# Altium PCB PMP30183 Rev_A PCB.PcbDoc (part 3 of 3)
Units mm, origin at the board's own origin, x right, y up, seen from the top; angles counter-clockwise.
Board outline 88.14 x 173.35 mm, 4 copper layers (Top Layer, Signal Layer 1, Signal Layer 2, Bottom Layer), stack 2.028 mm thick; 250 components, 133 nets, 589 pads, 226 vias.
Unrouted connection lines stored in the file: 1.
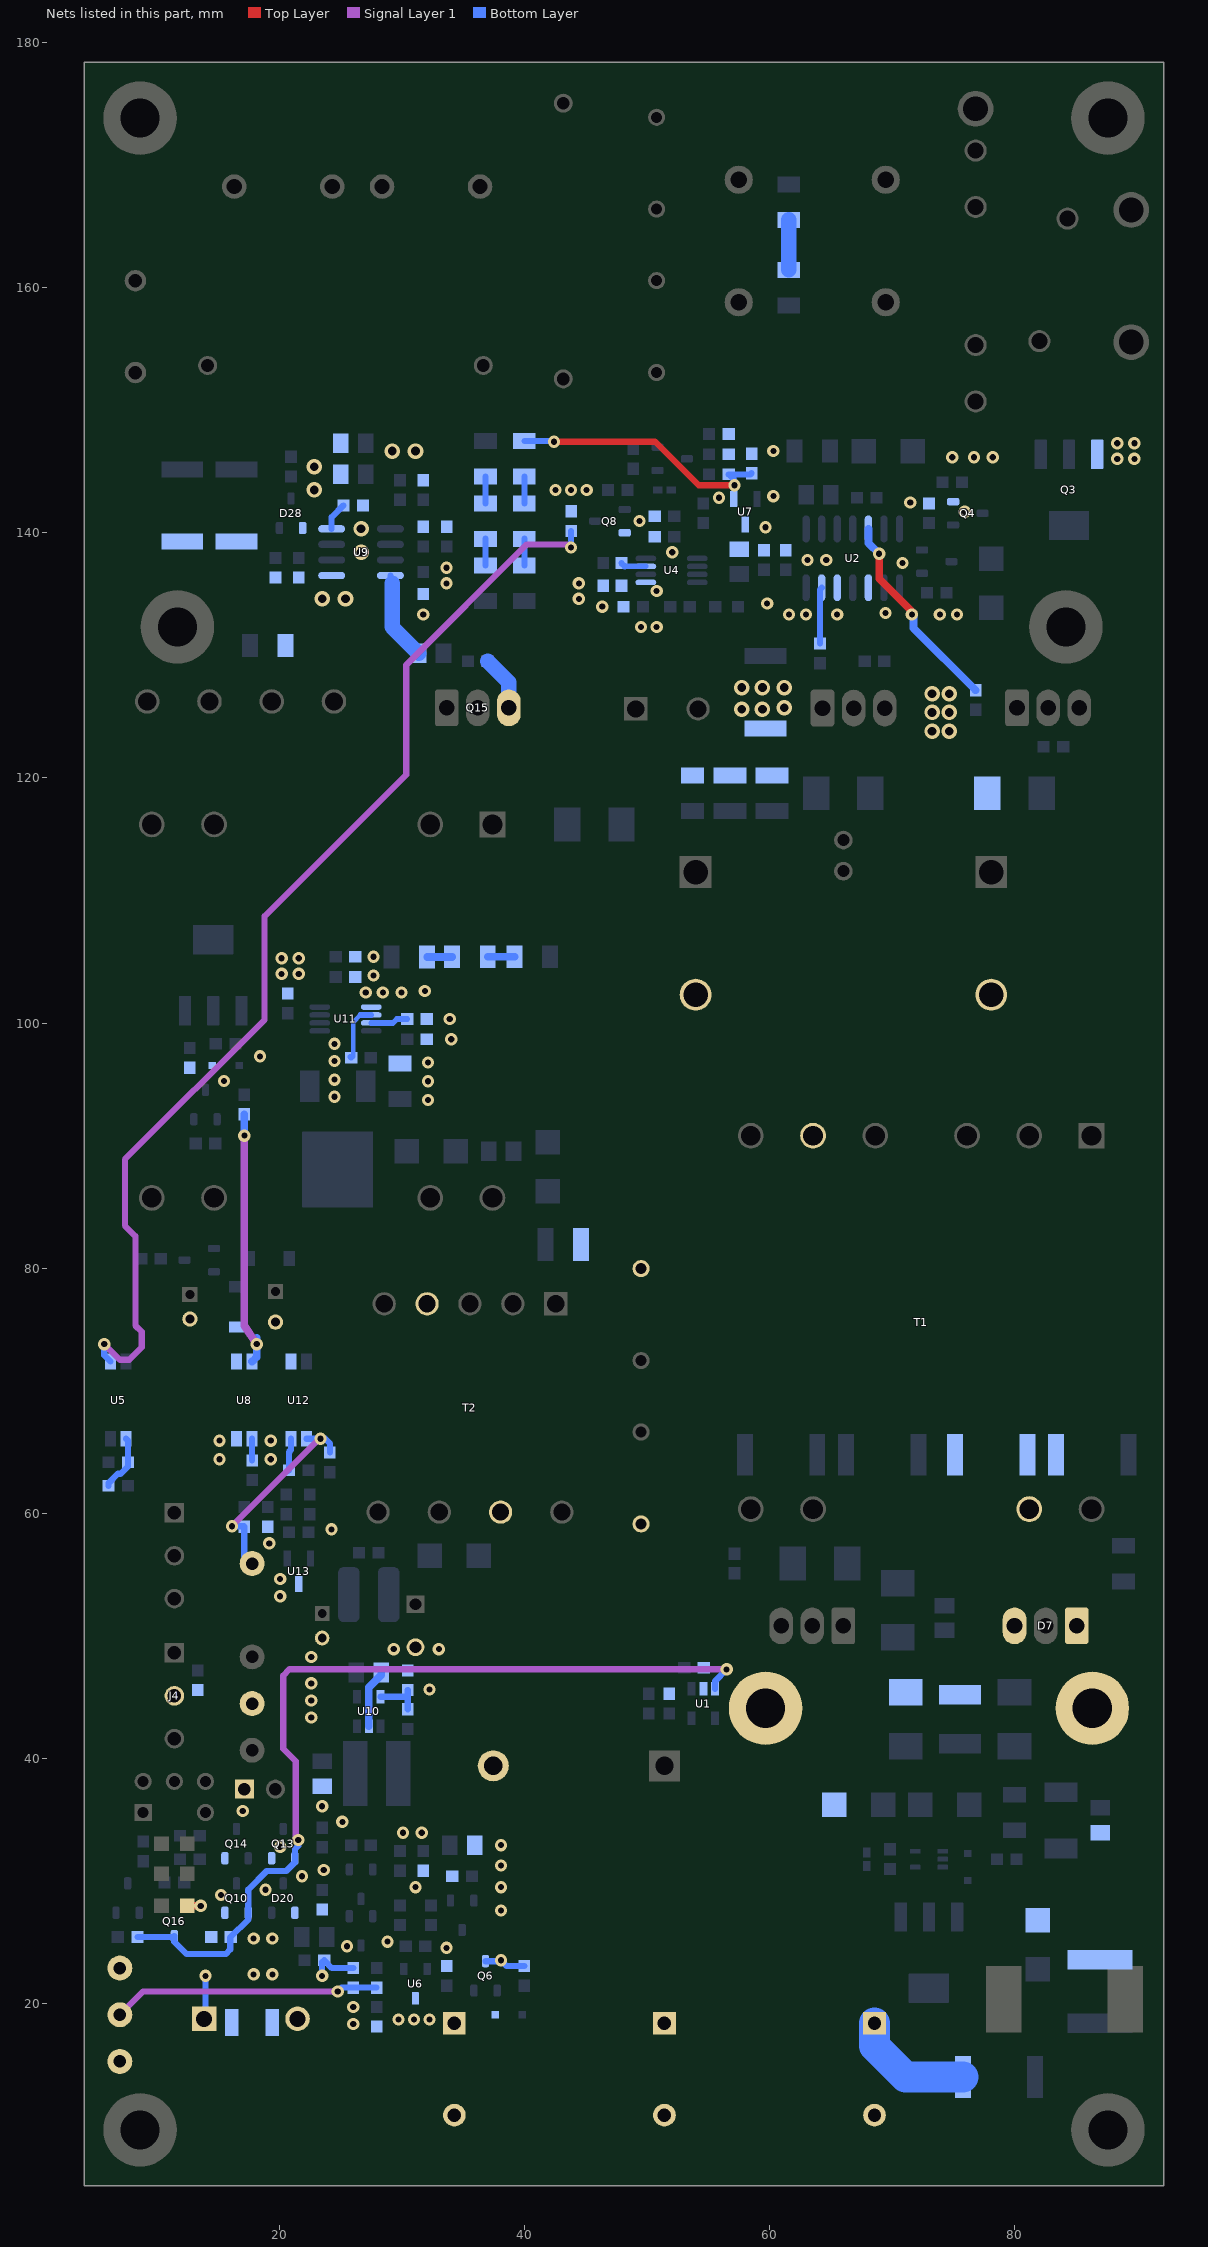
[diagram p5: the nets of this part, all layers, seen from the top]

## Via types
v1: diameter 1, hole 0.5, Top Layer to Bottom Layer, 163 vias
v2: diameter 1.27, hole 0.711, Top Layer to Bottom Layer, 63 vias

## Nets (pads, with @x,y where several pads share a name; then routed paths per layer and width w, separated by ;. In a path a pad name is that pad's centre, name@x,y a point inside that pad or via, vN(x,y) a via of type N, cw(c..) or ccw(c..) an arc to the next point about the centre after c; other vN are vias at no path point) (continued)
NetR7_1: R7.1 U2.12 | length 17.3
  Top Layer w0.635: v1@68.961,138.43 v1(68.961,138.303) 68.961,136.271 71.755,133.477 v1(71.628,133.35)
  Bottom Layer w0.635: U2.12@68.08,140.329 68.08,139.184 v1(68.961,138.303) ; v1(71.628,133.35) 71.755,133.477 71.755,132.245 R7.1@76.835,127.165
NetR9_1: R9.1 R12.2
NetR10_1: R10.1 U2.6 | length 4.6
  Bottom Layer w0.508: R10.1@64.135,130.975 64.135,135.393 U2.6@64.27,135.529
NetR19_1: R19.1 R23.2 U5.1 | length 4.7
  Bottom Layer w0.508: R19.1@6.058,62.23 6.058,62.442 6.829,63.213 7.041,63.213 7.658,63.83 R23.2@7.658,64.135 7.658,65.9 U5.1@7.493,66.065
NetR20_1: R20.1 R25.2 | length 2.2
  Bottom Layer w0.508: R20.1@40.005,137.34 R25.2@40.005,139.52
NetR25_1: R25.1 R29.2 | length 2.2
  Bottom Layer w0.508: R25.1@40.005,142.42 R29.2@40.005,144.6
NetR26_2: R26.2 U4.7 | length 2.1
  Bottom Layer w0.457: R26.2@48.204,137.267 U4.7@49.917,137.267
  Bottom Layer w0.508: R26.2@47.927,137.544 R26.2@48.204,137.267
NetR29_1: R29.1 R30.1 R38.2 U7.1 | length 21.7
  Top Layer w0.508: v1(42.418,147.447) 50.673,147.447 54.229,143.891 v1(57.15,143.891)
  Bottom Layer w0.508: R29.1@40.005,147.5 42.365,147.5 v1(42.418,147.447) ; v1(57.15,143.891) 57.089,143.891 57.089,144.371 R30.1@56.68,144.78 58.458,144.78 R38.2@58.547,144.869
NetR32_2: R32.2 R34.2 TP9.1 | length 21.9
  Signal Layer 1 w0.508: TP9.1@6.985,19.05 8.89,20.955 v1(24.765,20.955)
  Bottom Layer w0.508: v1(24.765,20.955) 25.075,21.265 R32.2@26.035,21.265 R34.2@27.94,21.265
NetR52_1: R52.1 U8.4 | length 21.2
  Signal Layer 1 w0.635: v1(17.145,90.805) 17.145,75.311 v1(18.161,73.787)
  Bottom Layer w0.635: v1(17.145,90.805) R52.1@17.145,92.545 ; U8.4@17.78,72.365 18.161,72.746 18.161,74.295
NetR53_1: R53.1 U8.1 | length 1.8
  Bottom Layer w0.508: R53.1@17.78,64.3 U8.1@17.78,66.065
NetR55_1: R55.1 R60.2 | length 4.1
  Bottom Layer w1.27: R55.1@61.595,161.47 R60.2@61.595,165.555
NetR56_1: R56.1 R59.2 | length 2.2
  Bottom Layer w0.508: R56.1@36.83,137.34 R59.2@36.83,139.52
NetR57_2: R57.2 U9.8 | length 7.3
  Bottom Layer w0.508: U9.8@29.07,136.525 29.07,136.03 29.21,135.89
  Bottom Layer w1.27: 29.21,135.89 29.21,132.334 R57.2@31.369,130.175
NetR59_1: R59.1 R62.2 | length 2.2
  Bottom Layer w0.508: R59.1@36.83,142.42 R62.2@36.83,144.6
NetR68_2: R68.2 U5.3 | length 90.5
  Signal Layer 1 w0.508: v1(5.715,73.787) 6.985,72.517 7.747,72.517 8.763,73.533 8.763,74.803 8.255,75.311 8.255,82.612 7.397,83.47 7.397,88.869 18.796,100.268 18.796,108.712 30.353,120.269 30.353,129.224 40.194,139.065 43.815,139.065 v1(43.815,138.811)
  Bottom Layer w0.508: v1(5.715,73.787) 5.715,72.873 U5.3@6.223,72.365 ; v1(43.815,138.811) R68.2@43.815,140.17
NetR69_2: R69.2 U9.4 | length 2.3
  Bottom Layer w0.508: U9.4@24.27,140.335 24.27,141.275 R69.2@25.235,142.24
NetR71_1: R71.1 R73.2 | length 2.2
  Bottom Layer w0.635: R73.2@37.01,105.41 R71.1@39.19,105.41
NetR73_1: R73.1 R75.2 | length 2
  Bottom Layer w0.635: R75.2@32.071,105.385 34.085,105.385 R73.1@34.11,105.41
NetR77_1: R77.1 R83.2 TP28.1 U12.1 | length 17.3
  Signal Layer 1 w0.508: v1(16.129,58.928) 23.266,66.065 v1(23.368,66.065)
  Bottom Layer w0.508: v1(16.129,58.928) 17.107,58.928 R83.2@17.145,58.89 17.145,56.515 TP28.1@17.78,55.88 ; U12.1@22.225,66.065 v1(23.368,66.065) 23.75,66.065 24.13,65.685 R77.1@24.13,64.935
NetR78_1: R78.1 R80.2 U10.5 | length 3.9
  Bottom Layer w0.508: U10.5@28.255,45.015 30.296,45.015 30.48,44.831 ; R78.1@30.48,43.98 30.48,44.831 ; R80.2@30.48,45.555 30.48,44.831
NetR79_1: R79.1 U11.6 | length 4.7
  Bottom Layer w0.381: R79.1@26.035,97.244 26.035,100.076 26.614,100.655
  Bottom Layer w0.457: R79.1@25.781,97.244 R79.1@25.87,97.155 ; 26.614,100.655 U11.6@27.5,100.655
NetR82_2: R82.2 U11.7 | length 3.1
  Bottom Layer w0.457: U11.7@27.5,100.005 29.266,100.005 29.591,100.33 R82.2@30.442,100.33
NetR84_2: R84.2 U12.2 | length 2.6
  Bottom Layer w0.508: R84.2@20.79,63.5 20.79,64.986 20.955,65.151 U12.2@20.955,66.065
OVER_TEMPERATURE: Q10.1 Q13.1 Q16.3 R43.2 R47.2 U1.3 | length 73.1
  Signal Layer 1 w0.508: v1(21.545,33.319) 21.336,33.528 21.336,39.751 20.32,40.767 20.32,46.736 20.828,47.244 50.165,47.244 v1(56.515,47.244)
  Bottom Layer w0.508: R43.2@8.42,25.4 11.36,25.4 Q16.3@11.43,25.47 11.43,25.019 12.446,24.003 15.621,24.003 16.002,24.384 16.002,25.362 R47.2@16.04,25.4 17.46,26.82 Q10.1@17.46,27.375 17.46,29.271 18.972,30.783 20.574,30.783 21.27,31.479 Q13.1@21.27,31.82 21.27,32.57 21.545,32.845 v1(21.545,33.319) ; U1.3@55.56,45.65 55.56,46.289 v1(56.515,47.244)
PGND: C1.2 C2.2 C3.2 C7.2 C15.1 C18.2 C21.2 C23.2 C24.2 C25.2 C27.2 C29.2 C32.2 C33.1 C35.2 C36.2 C39.2 C40.2 C41.2 C42.2 C43.2 C44.2 C45.2 C46.2 C50.2 C53.2 C54.2 C55.2 C56.2 C57.2 D8.2 D28.1 D29.2 D35.2 Q3.3 Q4.2 Q8.2 Q15.3 R14.1 R26.1 R38.1 R39.1 R51.2 R58.1 R61.2 R63.2 R66.1 R68.1 R69.1 R81.1 R82.1 T1.5 T2.4 U2.3 U2.5 U4.5 U7.3 U8.3 U9.1 U11.5 U12.3 | length 4.5
  Bottom Layer w1.27: R58.1@36.995,129.54 38.735,127.8 Q15.3@38.735,125.73
  other v1: 32.131,93.726 24.511,93.98 32.131,95.25 15.494,95.27 24.511,95.377 32.131,96.774 24.511,96.901 18.415,97.282 24.511,98.298 34.036,98.679 33.909,100.33 27.051,102.489 28.448,102.489 29.972,102.489 31.877,102.616 27.686,103.886 20.193,104.013 21.59,104.013 20.193,105.283 21.59,105.283 27.686,105.41 49.53,132.334 50.8,132.334 31.75,133.35 61.595,133.35 62.992,133.35 65.532,133.35 73.914,133.35 75.311,133.35 69.469,133.477 46.355,133.985 59.817,134.239 44.45,134.62 50.8,135.255 33.655,135.89 44.45,135.89 33.655,137.16 70.866,137.541 63.119,137.795 64.643,137.795 52.07,138.43 59.69,140.462 49.403,140.97 75.946,141.732 71.501,142.494 55.88,142.875 60.325,143.002 42.545,143.51 43.815,143.51 45.085,143.51 88.392,146.05 89.789,146.05 74.93,146.177 76.708,146.177 78.232,146.177 60.325,146.685 88.392,147.32 89.789,147.32
  other v2: 73.279,123.825 74.676,123.825 73.279,125.349 74.676,125.349 57.74,125.603 59.436,125.603 61.214,125.73 73.279,126.873 74.676,126.873 57.74,127.381 59.436,127.381 61.214,127.381 23.495,134.62 25.4,134.62 26.67,138.43 26.67,140.335 22.86,143.51 22.86,145.415 29.21,146.685 31.115,146.685
SGND: C5.2 C10.2 C11.2 C12.2 C13.2 C14.2 C16.2 C17.2 C20.2 C28.2 C31.2 C47.2 C48.2 C49.2 C51.2 C52.2 D7.1 D7.3 D11.2 D15.2 D16.2 D17.2 D20.1 D23.2 J2.2 J4.2 J5.1 Q10.2 Q13.2 Q14.2 Q16.2 R4.2 R12.1 R36.1 R40.2 R47.1 R48.2 R49.1 R80.1 R86.1 T1.11 T2.8 TP2.1 TP4.1 TP10.1 TP24.1 U1.2 U6.3 U8.2 U10.2 U13.3 | length 5.9
  Top Layer w0.635: D23.2@12.48,27.94 v1(13.589,27.94)
  Bottom Layer w0.635: U10.2@27.305,42.615 27.305,45.763 28.321,46.779 C51.2@28.321,46.99
  other v1: 26.035,18.288 29.718,18.669 30.988,18.669 32.258,18.669 26.035,19.685 17.907,22.352 19.431,22.352 33.655,24.511 25.527,24.638 28.829,25.019 17.907,25.273 19.431,25.273 38.1,27.559 15.24,28.829 18.87,29.25 31.115,29.464 38.1,29.464 21.844,30.353 23.622,30.861 38.1,31.242 20.066,32.766 38.1,32.893 30.099,33.909 31.623,33.909 25.146,34.798 17.018,35.687 23.495,36.068 22.606,43.307 22.606,44.704 32.258,45.593 22.606,46.101 22.606,48.26 29.337,48.895 33.02,48.895 20.066,53.213 20.066,54.61 19.177,57.531 24.257,58.674 15.113,64.389 19.304,64.389 15.113,65.913 19.304,65.913
VOUT: C10.1 C11.1 C12.1 C13.1 J2.1 L1.2 Q6.3 R21.1 R28.1 R32.1 R37.2 TP3.1 | length 21
  Bottom Layer w0.508: J2.1@13.865,18.715 13.97,18.82 v1(13.97,22.225) ; v1(23.495,22.225) 23.495,23.33 R37.2@23.66,23.495 24.29,22.865 R32.1@26.035,22.865 ; Q6.3@36.83,23.425 38.03,23.425 v1(38.1,23.495) 38.57,23.025 R21.1@40.005,23.025
  Bottom Layer w2.54: C11.1@68.58,18.355 68.58,16.51 71.12,13.97 R28.1@75.79,13.97
pads on no net: D10.2 D19.2 D20.2 D27.2 D28.2 D34.2 L4.2 L4.5 L4.7 L4.8 L4.11 L4.12 S1.1 S1.3 T1.1 T1.4 T1.6 T1.7 T1.12 T2.2 T2.6 T2.9 TP6.1 TP7.1 TP11.1 U2.4 U2.8 U2.9 U2.10 U2.14 U3.1 U10.1

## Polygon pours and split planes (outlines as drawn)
PGND on Bottom Layer "Bottom Layer-No Net 12" (solid, pour order 56): 18.415,151.765 36.195,151.765 38.1,149.86 70.066,149.86 71.755,148.171 71.922,148.171 72.773,147.32 79.502,147.32 80.645,148.463 90.932,148.463 91.44,147.955 91.44,80.01 90.17,78.74 48.895,78.74 42.545,72.39 41.91,71.755 5.08,71.755 4.445,72.39 4.445,121.285 5.715,122.555 13.335,122.555 15.875,125.095 15.875,133.985 13.335,136.525 9.525,136.525 8.89,137.16 8.89,141.605 9.525,142.24 18.185,142.24
+3.3VSEC on Bottom Layer "Bottom Layer-No Net 8" (solid, pour order 32): 9.906,42.672 10.414,43.18 15.621,43.18 16.383,42.418 17.78,42.418 19.685,42.418 20.32,43.053 21.463,43.053 22.225,42.291 23.622,42.291 24.765,42.291 25.908,41.148 27.178,41.148 27.559,40.767 27.559,36.322 26.797,35.56 25.527,35.56 24.892,36.195 24.892,36.322 24.765,36.449 24.765,38.608 24.511,38.862 16.002,38.862 14.478,37.338 13.081,37.338 12.573,37.846 12.573,38.227 12.573,39.497 12.065,40.005 10.668,40.005 9.906,40.767
NetC48_1 on Bottom Layer "Bottom Layer-No Net 7" (solid, pour order 30): 24.003,57.531 24.257,57.785 27.051,57.785 27.051,50.927 26.797,50.673 25.908,50.673 23.114,50.673 18.669,46.228 16.51,46.228 12.573,46.228 10.668,46.228 10.033,46.863 10.033,49.784 11.049,50.8 11.303,50.8 19.431,50.8 21.331,52.7 22.995,52.7 23.34,53.045 23.34,53.295 23.34,56.642
+12VSEC on Bottom Layer "Bottom Layer-No Net 6" (solid, pour order 28): 27.686,58.49 32.258,58.49 33.308,57.44 33.401,57.44 34.036,56.805 34.036,52.832 34.036,51.435 32.766,50.165 29.718,50.165 28.956,50.165 26.797,48.006 26.797,44.45 24.892,44.45 24.765,44.577 24.765,44.831 24.765,49.276 26.162,50.673 26.797,50.673 27.051,50.927 27.051,51.181 27.051,58.166
NetD32_2 on Bottom Layer "Bottom Layer-No Net 5" (solid, pour order 26): 21.463,91.313 32.512,91.313 32.385,91.186 32.385,87.503 33.147,86.741 35.179,86.741 35.814,86.106 35.814,85.344 37.592,83.566 37.592,81.28 37.592,79.375 36.449,78.232 36.449,76.708 35.941,76.2 35.179,76.2 34.544,76.835 34.544,77.07 34.544,78.359 33.401,79.502 25.146,79.502 23.622,81.026 23.622,82.677 21.463,84.836
NetF1_2 on Bottom Layer "Bottom Layer-No Net" (solid, pour order 0): 73.025,177.8 81.915,177.8 82.55,177.165 82.55,168.91 78.105,164.465 73.025,164.465 72.39,165.1 72.39,177.165
NetF1_1 on Bottom Layer "Bottom Layer-No Net 1" (solid, pour order 2): 66.675,162.56 80.01,162.56 84.455,158.115 84.455,152.4 83.82,151.765 80.01,151.765 77.47,149.225 74.295,149.225 66.675,156.21
NetC37_2 on Bottom Layer "Bottom Layer-No Net 2" (solid, pour order 6): 21.59,177.8 57.785,177.8 59.055,176.53 59.055,175.26 59.055,166.37 58.42,165.735 58.315,165.63 55.245,165.63 52.6,168.275 50.165,168.275 48.895,168.275 47.625,167.005 41.275,167.005 39.37,168.91 39.37,170.18 37.465,172.085 36.83,172.085 27.135,172.085 26.035,170.985 26.035,170.815 26.035,167.005 25.4,166.37 21.59,166.37 20.32,167.64 20.32,177.777
NetC34_2 on Bottom Layer "Bottom Layer-No Net 3" (solid, pour order 8): 33.972,170.815 37.148,170.815 38.417,169.545 38.417,168.275 40.957,165.735 43.497,165.735 45.72,163.195 49.485,158.115 52.387,158.115 54.567,160.295 54.567,160.43 55.427,161.29 58.737,161.29 59.372,160.655 59.372,153.035 58.102,151.765 57.468,151.13 41.593,151.13 40.322,151.13 39.688,151.765 39.688,152.4 39.688,155.575 33.337,161.925 33.337,170.18
NetL8_2 on Bottom Layer "Signal Layer 2-No Net 1" (solid, pour order 12): 6.35,168.91 10.16,168.91 11.43,168.91 14.605,172.085 17.78,172.085 19.05,170.815 19.05,159.385 15.875,156.21 6.985,156.21 6.35,156.845 6.35,168.275 6.985,168.91
NetC38_2 on Bottom Layer "Signal Layer 2-No Net 2" (solid, pour order 14): 4.445,125.095 4.445,123.825 5.08,123.19 11.43,123.19 12.065,123.825 12.065,137.795 9.525,137.795 9.525,140.97 18.185,140.97 18.415,140.97 19.05,141.605 19.05,145.415 19.685,146.05 21.68,146.05 21.68,146.14 22.225,146.685 22.225,153.035 20.32,154.94 12.065,154.94 11.43,154.305 11.43,151.13 4.445,144.145
NetD6_1 on Bottom Layer "Bottom Layer-No Net 4" (solid, pour order 22): 81.407,143.637 82.423,143.637 82.677,143.637 83.82,144.78 83.82,147.701 83.947,147.828 84.963,147.828 85.09,147.701 85.09,144.78 85.217,144.653 86.233,143.637 90.932,143.637 91.694,142.875 91.694,135.255 90.805,134.366 87.884,134.366 86.233,136.017 77.724,136.017 77.089,136.652 77.089,138.94 77.091,138.94 79.121,140.97 79.121,142.113 79.883,142.113 81.407,143.637
NetC17_1 on Bottom Layer "Bottom Layer-No Net 9" (solid, pour order 40): 73.025,41.275 75.565,41.275 75.565,33.655 75.01,33.1 73.66,33.1 73.725,33.035 73.725,30.675 75.92,28.48 76.2,28.2 76.2,26.035 76.07,25.905 75.675,25.905 74.295,25.905 74.295,26.035 74.295,28.575 72.325,30.545 72.325,30.675 72.39,30.74 72.39,34.29 73.025,34.29 73.37,34.999 73.37,39.63
SGND on Bottom Layer "Bottom Layer-No Net 10" (solid, pour order 46): 4.445,66.675 43.18,66.675 47.625,62.23 52.705,62.23 52.705,69.215 91.44,69.215 91.44,5.715 5.08,5.715 4.445,6.35
+400V on Top Layer "Top Layer-No Net 8" (solid, pour order 54): 46.101,114.211 55.334,114.211 56.134,113.411 75.692,113.411 76.962,114.681 81.788,114.681 83.058,113.411 83.058,108.712 80.391,106.045 49.276,106.045 46.101,109.22
NetC38_1 on Top Layer "Bottom Layer-No Net 11" (solid, pour order 50): 44.45,114.3 44.45,112.395 43.434,111.379 24.13,111.379 24.13,114.935 34.29,114.935 34.925,114.3 38.735,114.3 39.37,114.3
NetC1_1 on Top Layer "Top Layer-No Net 7" (solid, pour order 52): 52.828,117.475 53.975,117.475 59.055,122.555 80.518,122.555 81.661,123.698 81.661,127 81.915,127.254 83.693,127.254 83.947,127 83.947,123.19 74.803,114.046 56.769,114.046 56.134,114.681 52.839,114.681
NetD25_2 on Top Layer "Top Layer-No Net 6" (solid, pour order 48): 34.925,127.635 34.955,127.605 37.465,127.605 38.1,126.97 38.1,123.19 50.8,123.19 52.07,124.46 52.07,127 52.705,127.635 55.245,127.635 55.632,127.248 55.88,127.248 55.88,121.92 53.34,119.38 50.8,119.38 41.275,119.38 40.64,118.745 40.64,118.465 40.64,114.935 40.005,114.3 34.925,114.3 34.29,114.935 34.29,123.19 34.925,123.825
NetL5_2 on Top Layer "Top Layer-No Net" (solid, pour order 4): 66.675,177.165 80.645,177.165 81.915,175.895 81.915,174.625 81.915,172.085 85.09,168.91 85.725,168.275 85.725,165.1 85.725,163.195 91.44,157.48 91.44,156.21 91.44,153.035 90.805,152.4 73.66,152.4 66.675,159.385 66.675,160.655
NetC38_1 on Top Layer "Top Layer-No Net 1" (solid, pour order 20): 4.414,155.575 37.66,155.575 38.93,154.305 38.93,152.595 35.56,149.225 19.054,149.225 19.054,141.605 19.054,128.841 28.003,128.841 30.48,126.365 30.48,114.3 27.559,111.379 4.431,111.379 4.431,136.525 4.431,151.589
NetQ2_3 on Top Layer "Top Layer-No Net 2" (solid, pour order 24): 57.785,132.461 67.183,132.461 72.136,127.508 72.136,126.492 72.136,124.968 71.378,124.21 71.247,124.21 68.707,124.21 68.203,124.714 68.199,124.714 68.199,127.254 66.421,129.032 57.74,129.032
NetC4_2 on Top Layer "Signal Layer 1-No Net 2" (solid, pour order 34): 59.69,61.595 66.675,61.595 67.9,62.82 67.945,62.82 73.66,62.82 73.66,55.535 71.338,53.213 71.12,53.213 70.993,53.34 68.5,53.34 68.5,50.085 67.34,48.925 64.135,48.925 64.105,48.895 62.865,48.895 59.69,48.895 59.69,52.07
NetC6_1 on Top Layer "Top Layer-No Net 3" (solid, pour order 38): 62.269,52.157 62.817,52.705 62.865,52.705 62.868,52.702 64.066,52.702 64.515,52.254 64.586,52.254 64.734,52.106 64.734,49.069 64.908,48.895 71.755,48.895 76.073,53.213 76.2,53.213 83.82,53.213 84.328,52.705 84.455,52.705 84.455,48.895 84.455,48.133 79.502,43.18 72.39,43.18 65.405,43.18 63.5,45.085 63.5,45.72 63.5,46.99 62.23,48.26
NetC28_1 on Top Layer "Top Layer-No Net 4" (solid, pour order 42): 84.455,26.035 91.44,26.035 91.44,15.24 89.535,13.335 88.265,13.335 84.455,13.335 83.82,13.335 82.55,12.065 79.42,12.065 79.375,12.02 79.375,15.645 83.59,15.645 83.82,15.875 83.82,25.4 84.455,26.035
VOUT on Top Layer "Top Layer-No Net 5" (solid, pour order 44): 33.02,43.18 33.655,43.815 46.99,43.815 48.26,42.545 48.26,37.465 51.435,34.29 61.595,34.29 65.405,30.48 68.58,27.305 68.58,20.955 69.85,19.685 69.85,16.51 70.485,15.875 70.485,5.715 5.08,5.715 4.445,6.35 4.445,17.145 5.08,17.78 8.255,17.78 9.525,19.05 9.525,21.59 11.43,23.495 23.495,23.495 24.105,23.495 31.75,31.14 31.775,31.14 33.02,32.385
SGND on Signal Layer 2 "Signal Layer 2-No Net 4" (solid, pour order 64): 4.445,66.675 43.18,66.675 47.625,62.23 52.705,62.23 52.705,69.215 91.44,69.215 91.44,5.715 5.08,5.715 4.445,6.35
PGND on Signal Layer 2 "Signal Layer 2-No Net 3" (solid, pour order 58): 5.08,154.94 37.465,154.94 38.735,153.67 38.735,149.86 70.066,149.86 70.066,149.644 72.39,147.32 79.502,147.32 80.518,148.336 90.805,148.336 91.059,148.336 91.109,148.286 91.44,147.955 91.44,80.01 90.17,78.74 48.895,78.74 41.91,71.755 5.08,71.755 4.47,72.365 4.47,154.33 5.08,154.94
EARTH on Signal Layer 2 "Signal Layer 2-No Net" (solid, pour order 10): 47.43,168.91 48.7,170.18 49.53,170.18 51.435,170.18 52.07,170.18 55.88,166.37 68.58,166.37 71.755,166.37 74.295,163.83 79.375,163.83 80.01,163.195 85.725,163.195 86.995,164.465 86.995,167.64 83.185,171.45 83.185,177.8 91.44,177.8 91.44,160.83 89.765,159.155 73.255,159.155 70.485,161.925 67.31,161.925 66.675,161.29 55.537,161.29 53.05,158.75 49.628,158.75 47.43,160.655 47.43,161.925 47.43,163.83
NetC8_1 on Signal Layer 1 "Signal Layer 1-No Net 5" (solid, pour order 62): 84.074,126.746 84.582,127.254 86.36,127.254 88.519,125.095 88.519,99.314 83.82,94.615 79.756,94.615 78.994,94.615 78.486,94.107 78.486,92.837 78.486,90.297 77.216,89.027 75.072,89.027 74.583,89.516 74.295,89.804 74.295,89.916 74.295,96.901 76.708,99.314 80.137,99.314 81.788,100.965 81.788,103.886 81.788,115.57 81.788,122.047 83.439,123.698 83.947,123.698 84.074,123.825 84.074,126.619
NetD4_2 on Signal Layer 1 "Signal Layer 1-No Net 4" (solid, pour order 60): 66.04,127 67.945,127 67.945,123.825 68.58,123.19 73.66,118.11 73.66,91.44 73.66,89.535 74.93,88.265 77.47,88.265 79.121,89.916 79.121,93.091 79.375,93.345 80.01,93.345 83.185,93.345 83.82,92.71 83.82,83.82 81.915,81.915 81.28,81.915 71.755,81.915 70.485,83.185 69.85,83.82 69.85,88.9 70.485,89.535 70.485,92.075 69.85,92.71 67.945,94.615 67.945,97.155 67.945,111.125 67.945,117.475 66.175,119.245 66.04,119.245
NetD26_3 on Signal Layer 1 "Signal Layer 1-No Net" (solid, pour order 16): 4.445,154.94 5.08,155.575 11.755,155.575 12.065,155.575 12.7,154.94 12.7,137.795 16.51,133.985 16.51,125.095 15.875,124.46 5.08,124.46 4.997,124.46 4.445,125.012
NetD26_2 on Signal Layer 1 "Signal Layer 1-No Net 1" (solid, pour order 18): 20.32,170.18 22.225,172.085 31.115,172.085 32.385,170.815 33.02,170.18 33.02,149.86 22.225,148.463 22.225,130.175 22.225,125.095 21.59,124.46 18.419,124.46 17.145,124.46 16.51,125.095 16.51,132.715 13.97,135.255 13.97,154.94 20.32,161.29
NetC6_1 on Signal Layer 1 "Signal Layer 1-No Net 3" (solid, pour order 36): 59.69,53.34 59.817,53.213 69.215,53.213 70.485,51.943 70.485,51.435 70.485,37.681 64.554,31.75 50.165,31.75 46.99,34.925 46.355,35.56 46.355,40.64 48.895,43.18 55.245,43.18 57.785,40.64 61.595,40.64 63.5,42.545 63.5,45.72 59.69,49.53

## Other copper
Top Layer:
  rectangle net NetD15_1: 70.485,17.145 83.185,24.765
  rectangle net NetC28_1: 86.995,17.018 91.059,23.555
Signal Layer 1:
  rectangle net +400V: 45.974,111.379 50.8,127.254
Bottom Layer:
  rectangle net SGND: 56.139,42.672 57.658,45.986
  rectangle net SGND: 18.796,17.145 22.352,19.815
  rectangle net VOUT: 12.875,17.272 16.637,19.713
  rectangle net NetC8_1: 81.153,117.348 86.106,120.142
  rectangle net NetD4_2: 67.31,117.348 72.263,120.142
  rectangle net +400V: 45.974,111.506 49.149,117.602
  rectangle net NetC38_1: 41.021,111.506 44.45,117.602
  rectangle net NetC1_1: 62.433,114.681 65.405,120.739
  rectangle net NetC1_1: 52.705,114.554 65.405,118.11
  rectangle net NetQ2_3: 57.658,128.524 62.23,132.461
  rectangle net NetC4_2: 68.58,60.915 73.7,66.675
  rectangle net NetR5_2: 59.69,62.23 67.945,66.675
  rectangle net NetR9_1: 78.105,62.82 87.63,66.675
  rectangle net NetC17_1: 69.215,39.37 82.55,43.18
  rectangle net NetD15_1: 70.485,17.145 83.185,24.765
  rectangle net EARTH: 84.37,5.715 91.44,19.05
  rectangle net NetC28_1: 79.375,12.02 82.59,15.645

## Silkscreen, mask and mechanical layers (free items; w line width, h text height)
Top Overlay:
  lines w0.2: 7.112,55.245 7.112,58.801
  lines w0.254: 86.868,162.433 88.011,163.576 89.789,163.576 91.059,163.576 89.916,162.433 ; 87.884,162.433 89.027,163.576 ; 88.9,162.433 90.043,163.576 ; 89.535,163.576 89.535,164.846
  text "~" at 77.724,172.339 h3.05 r334.65
  text "~" at 87.249,155.575 h3.05 r334.65
  text "30V" at 4.953,64.262 h1.02 r270
  text "18V" at 6.35,64.135 h1.02 r270
  text "CLIP" at 5.588,58.801 h1.02 r270
  text "REMOTE" at 4.826,54.991 h1.02 r270
  text "ON" at 6.35,53.721 h1.02 r270
  text "12V" at 6.35,49.657 h1.02 r270
  text "GND" at 6.35,46.228 h1.02 r270
  text "3.3V" at 6.35,42.545 h1.02 r270
  text "30V" at 6.096,35.179 h1.02 r270
  text "18V" at 4.826,32.258 h1.02 r270
  text "3.3V" at 6.35,29.972 h1.02 r270
  text ".PRJ_Number" at 54.737,25.4 h1.52
  text ".PCB_Rev" at 69.342,25.4 h1.52
  text "-" at 67.056,25.146 h2.03
  text "+" at 13.97,12.065 h2.03 r180
  text "-" at 22.225,12.065 h2.03 r180
  text "Vout" at 14.605,6.985 h2
M1 Board Outline:
  the board outline again, w0.254
M2 Board Dimensions:
  rectangle: 0,-6.985 3.175,-3.81
  rectangle: 3.175,-10.16 12.7,-6.985
  lines w0.178: 0,-6.985 25.4,-6.985 ; 3.175,-10.16 3.175,-3.81 ; 6.35,-10.16 6.35,-3.81 ; 12.7,-10.16 12.7,-3.81 ; 19.05,-10.16 19.05,-3.81 ; 0,-10.16 25.4,-10.16 25.4,-3.81 0,-3.81 0,-10.16
M5 Assembly Top:
  circle w0.254: c8.636,173.863 r1.709
  circle w0.254: c87.63,173.863 r1.709
  circle w0.254: c87.63,9.652 r1.709
  circle w0.254: c8.636,9.652 r1.709
  lines w0.254: -7.417,-23.626 160.223,-23.626 ; -7.417,-18.462 160.274,-18.462 ; -7.417,-13.297 -7.417,-28.791 94.31,-28.791 160.274,-28.791 160.274,-13.297 -7.404,-13.297 -7.404,-28.791 32.614,-28.791 ; 5.715,128.27 90.17,128.27 ; 5.715,132.334 90.17,132.334 ; 11.176,177.8 11.176,176.784 ; 11.684,128.27 11.684,119.38 22.479,119.38 22.479,128.27 ; 12.192,176.784 11.176,176.784 ; 15.875,181.483 11.176,176.784 ; 30.734,128.27 30.734,119.38 41.529,119.38 41.529,128.27 ; 46.355,128.27 46.355,119.38 57.15,119.38 57.15,128.27 ; 53.975,44.069 92.075,44.069 ; 53.975,48.133 92.075,48.133 ; 55.194,-28.791 55.194,-13.297 ; 58.166,47.625 58.166,56.515 68.961,56.515 68.961,47.625 ; 61.468,128.27 61.468,119.38 72.263,119.38 72.263,128.27 ; 77.216,47.625 77.216,56.515 88.011,56.515 88.011,47.625 ; 77.47,128.27 77.47,119.38 88.265,119.38 88.265,128.27 ; 87.376,-18.462 87.376,-13.297 ; 108.712,-18.462 108.712,-13.297 ; 124.511,-28.956 124.511,-23.804 ; 5.715,123.19 90.17,123.19 90.17,148.463 5.715,148.463 5.715,123.19 ; 53.975,27.94 92.075,27.94 92.075,53.213 53.975,53.213 53.975,27.94
  text "Hole Diameter: 3.2mm" at 17.145,182.626 h1.52
  text "COMPONENTS MARKED 'DNP' SHOULD NOT BE POPULATED." at 29.299,-8.09 h1.52
  text "ASSEMBLY VARIANT:" at 29.286,-11.024 h1.52
  text ".VariantName" at 55.601,-11.024 h1.52
  text "PCB VIEWED FROM TOP SIDE" at -5.804,-16.654 h1.52
  text "BOARD #:" at 57.099,-16.654 h1.52
  text ".PRJ_Number" at 70.955,-16.654 h1.52
  text "REV:" at 92.405,-16.654 h1.52
  text ".PCB_Rev" at 99.809,-16.654 h1.52
  text "SVN REV:" at 113.69,-16.654 h1.52
  text ".VersionControl_RevNumber" at 126.543,-16.654 h1.52
  text "TID #:" at 57.099,-21.819 h1.52
  text ".TID" at 70.955,-21.819 h1.52
  text "PLOT NAME =" at -5.804,-27.034 h1.52
  text ".plot_File_Name" at 14.656,-27.034 h1.52
  text "GENERATED    :" at 57.15,-27.034 h1.52
  text ".Print_Date" at 79.235,-27.034 h1.52
  text ".Print_Time" at 97.752,-27.034 h1.52
  text "TEXAS INSTRUMENTS" at 129.87,-27.034 h1.52
M6 Assembly Bottom:
  lines w0.254: -7.429,-18.474 160.261,-18.474 ; -7.379,-23.639 160.261,-23.639 ; 28.334,-28.969 28.334,-23.817 ; 44.133,-18.474 44.133,-13.31 ; 65.468,-18.474 65.468,-13.31 ; 97.65,-28.804 97.65,-13.31 ; 120.231,-28.804 160.249,-28.804 160.249,-13.31 -7.429,-13.31 -7.429,-28.804 58.534,-28.804 160.261,-28.804 160.261,-13.31
  text "COMPONENTS MARKED 'DNP' SHOULD NOT BE POPULATED." at 154.991,-8.077 h1.52
  text ".VariantName" at 128.473,-11.024 h1.52
  text "ASSEMBLY VARIANT:" at 154.864,-11.024 h1.52
  text ".VersionControl_RevNumber" at 26.302,-16.667 h1.52
  text "SVN REV:" at 39.154,-16.667 h1.52
  text ".PCB_Rev" at 53.035,-16.667 h1.52
  text "REV:" at 60.439,-16.667 h1.52
  text ".PRJ_Number" at 81.89,-16.667 h1.52
  text "BOARD #:" at 95.745,-16.667 h1.52
  text "PCB VIEWED FROM BOTTOM SIDE" at 149.225,-21.717 h1.52
  text ".TID" at 81.89,-21.831 h1.52
  text "TID #:" at 95.745,-21.831 h1.52
  text "TEXAS INSTRUMENTS" at 22.974,-27.047 h1.52
  text ".Print_Time" at 55.093,-27.047 h1.52
  text ".Print_Date" at 73.609,-27.047 h1.52
  text "GENERATED    :" at 95.694,-27.047 h1.52
  text ".plot_File_Name" at 138.189,-27.047 h1.52
  text "PLOT NAME =" at 158.648,-27.047 h1.52
M9 Title Sheet:
  drawing of 57 lines, arcs and shapes, not listed
  text "1" at 18.792,204.127 h1.78
  text "2" at 82.182,204.127 h1.78
  text "3" at 145.411,204.127 h1.78
  text "4" at 209.08,204.127 h1.78
  text "5" at 272.555,204.127 h1.78
  text "6" at 336.182,204.127 h1.78
  text "A" at -10.579,175.095 h1.78
  text "A" at 365.341,175.095 h1.78
  text "B" at -10.579,114.643 h1.78
  text "B" at 365.341,114.643 h1.78
  text "C" at -10.104,55.858 h1.78
  text "C" at 365.341,54.318 h1.78
  text "PROJECT TITLE:" at 288.125,7.048 h1.14
  text ".PRJ_Title" at 289.395,3.662 h1.78
  text "DESIGNED FOR:" at 288.125,-0.597 h1.14
  text ".PRJ_Customer" at 289.395,-4.153 h1.78
  text "D" at -10.579,-5.88 h1.78
  text "D" at 365.341,-5.88 h1.78
  text "FILE NAME:" at 288.125,-8.217 h1.14
  text ".PCB_File_Name_No_Path" at 289.395,-11.265 h1.78
  text "Texas Instruments (TI) and/or its licensors do not warrant the accuracy or completeness of this specification" at 161.9,-15.376 h1.14
  text "ENGINEER:" at 288.125,-15.583 h1.14
  text "LAYOUT BY:" at 326.352,-15.583 h1.14
  text "or any information contained therein. TI and/or its licensors do not warrant that this design will meet" at 160.757,-18.237 h1.14
  text ".PRJ_Engineer" at 289.395,-19.52 h1.78
  text ".PCB_Layout" at 327.635,-19.52 h1.78
  text "the specifications, will be suitable for your application or fit for any particular purpose, or will operate in" at 160.757,-21.099 h1.14
  text "ALTIUM DESIGNER VERSION:" at 326.352,-23.457 h1.14
  text "an implementation. TI and/or its licensors do not warrant that the design is production worthy. You should" at 160.757,-23.961 h1.14
  text "completely validate and test your design implementation to confirm the system functionality for your application." at 161.9,-26.822 h1.14
  text ".print_Scale" at 289.395,-26.843 h1.78
  text ".Application_BuildNumber" at 327.635,-26.843 h1.78
  text "1" at 18.792,-32.093 h1.78
  text "2" at 82.182,-32.093 h1.78
  text "3" at 145.411,-32.093 h1.78
  text "4" at 209.08,-32.093 h1.78
  text "5" at 272.555,-32.093 h1.78
  text "6" at 336.182,-32.093 h1.78
M10 Fab Notes:
  drawing of 185 lines, arcs and shapes, not listed
  text "DESIGN INFORMATION" at 314.478,150.114 h1.52
  text "MIN. TRACK WIDTH:" at 298.106,145.542 h1.52
  text "8" at 325.951,145.542 h1.52
  text "MIL" at 329.881,145.542 h1.52
  text "MIN. CLEARANCE:" at 298.106,142.189 h1.52
  text "0.2" at 324.427,142.189 h1.52
  text "mm" at 329.881,142.189 h1.52
  text "MIN. VIA PAD SIZE:" at 298.106,138.836 h1.52
  text "24" at 325.189,138.836 h1.52
  text "MIL" at 329.881,138.836 h1.52
  text "0.05mm (2MIL)" at 315.759,135.237 h1.52
  text "MINIMUM ANNULAR RING" at 289.744,135.128 h1.52
  text "EXTERNAL" at 333.742,135.128 h1.52
  text "PER" at 294.824,132.131 h1.52
  text "IPC-D-275 CLASS 2 LEVEL C" at 300.412,132.131 h1.52
  text "MIL, HOLES" at 338.213,129.279 h1.52
  text "+/-" at 328.244,129.261 h1.52
  text "+/-" at 349.936,129.261 h1.52
  text "REGISTRATION TOLERANCES:" at 289.744,129.134 h1.52
  text "METAL" at 320.218,129.134 h1.52
  text "5" at 334.853,129.134 h1.52
  text "3" at 356.012,129.134 h1.52
  text "MIL" at 358.964,129.134 h1.52
  text "MATERIAL:" at 287.844,123.813 h1.52
  text "FR-4 High Tg" at 312.9,120.249 h1.52
  text "FR-408" at 298.538,120.031 h1.52
  text "X" at 309.003,120.031 h1.52
  text "OTHER" at 336.333,120.031 h1.52
  text "62 MIL (1.6mm) +/-10%" at 306.668,115.898 h1.52
  text "THICKNESS:" at 289.744,115.789 h1.52
  text "X" at 303.413,115.789 h1.52
  text "OTHER" at 339.305,115.789 h1.52
  text "TOLERANCE:" at 289.744,111.776 h1.52
  text "X" at 311.062,111.776 h1.52
  text "ANSI IPC-6012 TYPE 3 CLASS 2" at 315.81,111.776 h1.52
  text "OTHER +/-" at 315.81,107.814 h1.52
  text "BOW & TWIST:" at 289.744,103.826 h1.52
  text "X" at 311.062,103.826 h1.52
  text "ANSI IPC-6012 TYPE 3 CLASS 2" at 315.81,103.826 h1.52
  text "OTHER +/-" at 315.81,99.8 h1.52
  text "DRILLING:" at 287.844,96.282 h1.52
  text "REFERENCE:" at 289.744,93.31 h1.52
  text "X" at 306.209,93.31 h1.52
  text "AS SHOWN" at 310.958,93.31 h1.52
  text "X" at 329.094,93.31 h1.52
  text "NC_DRILL FILES" at 332.574,93.31 h1.52
  text "PTH MIN COPPER THICKNESS:" at 289.744,89.297 h1.52
  text "X" at 324.039,89.297 h1.52
  text "1MIL" at 327.519,89.297 h1.52
  text "OTHER" at 340.143,89.297 h1.52
  text "BOARD FINISH:" at 287.844,85.259 h1.52
  text "SILKSCREEN:" at 291.787,82.261 h1.52
  text "X" at 315.886,82.261 h1.52
  text "TOP" at 319.086,82.261 h1.52
  text "X" at 328.84,82.261 h1.52
  text "BOTTOM" at 332.066,82.261 h1.52
  text "SILKSCREEN COLOR:" at 291.787,78.02 h1.52
  text "X" at 315.86,78.02 h1.52
  text "WHITE" at 319.086,78.02 h1.52
  text "OTHER" at 332.066,78.02 h1.52
  text "SOLDER RESIST COLOR:" at 291.787,73.702 h1.52
  text "X" at 306.208,69.658 h1.52
  text "GREEN" at 309.434,69.658 h1.52
  text "BLUE" at 324.446,69.658 h1.52
  text "OTHER" at 338.111,69.658 h1.52
  text "IMMERSION GOLD (ENIG)" at 314.794,64.87 h1.52
  text "ENEPIG" at 348.767,64.786 h1.52
  text "SURFACE FINISH:" at 287.844,64.761 h1.52
  text "X" at 310.045,64.761 h1.52
  text "IMM. TIN/SILVER OR EQUIV" at 296.215,60.773 h1.52
  text "OTHER" at 332.574,60.773 h1.52
  text "ARRAY/PANEL:" at 287.844,56.226 h1.52
  text "CUT AND TRIM PER MECH LAYER 1" at 314.794,56.118 h1.52
  text "N.C. ROUTE" at 314.794,52.264 h1.52
  text "X" at 332.04,52.264 h1.52
  text "V. SCORE" at 336.79,52.264 h1.52
  text "CERTIFICATION:" at 287.844,48.784 h1.52
  text "MATERIALS AND WORKMANSHIP FOR ALL PCBS" at 306.259,48.784 h1.52
  text "TO MEET OR EXCEED THE REQUIREMENTS OF:" at 306.259,46.295 h1.52
  text "X" at 296.773,42.828 h1.52
  text "ANSI IPC-A-600F CLASS ->" at 300.303,42.828 h1.52
  text "X" at 341.935,42.828 h1.52
  text "2" at 344.956,42.828 h1.52
  text "1" at 336.955,42.79 h1.52
  text "3" at 353.948,42.79 h1.52
  text "X" at 296.825,38.777 h1.52
  text "UL 94V-0" at 300.303,38.777 h1.52
  text "X" at 317.45,38.777 h1.52
  text "RoHS" at 320.928,38.777 h1.52
  text "OTHER" at 337.296,38.777 h1.52
  text "PER ORDER" at 347.381,38.777 h1.52
  text "ADDITIONAL REQUIREMENTS:" at 287.844,35.195 h1.52
  text "MICROSECTION:" at 289.744,32.274 h1.52
  text "YES" at 312.749,32.274 h1.52
  text "REQUIRED" at 334.631,28.308 h1.52
  text "BARE BOARD ELEC. TEST:" at 289.744,28.236 h1.52
  text "NONE" at 322.909,28.236 h1.52
  text "X" at 331.405,28.236 h1.52
  text "PER ORDER" at 349.668,28.236 h1.52
  text "MANUFACTURER'S UL:" at 289.744,24.248 h1.52
  text "RAIL" at 319.353,24.139 h1.52
  text "METAL" at 331.845,24.139 h1.52
  text "X" at 341.376,24.13 h1.52
  text "SILK" at 344.842,24.139 h1.52
M11 Gerber Information:
  lines w0.254: -7.417,-23.626 160.223,-23.626 ; -7.417,-18.462 160.274,-18.462 ; -7.417,-13.297 -7.417,-28.791 94.31,-28.791 160.274,-28.791 160.274,-13.297 -7.404,-13.297 -7.404,-28.791 32.614,-28.791 ; 55.194,-28.791 55.194,-13.297 ; 87.376,-18.462 87.376,-13.297 ; 108.712,-18.462 108.712,-13.297 ; 124.511,-28.956 124.511,-23.804
  text "ALL ARTWORK VIEWED FROM TOP SIDE" at -5.804,-16.654 h1.52
  text "BOARD #:" at 57.099,-16.654 h1.52
  text ".PRJ_Number" at 70.955,-16.654 h1.52
  text "REV:" at 92.405,-16.654 h1.52
  text ".PCB_Rev" at 99.809,-16.654 h1.52
  text "SVN REV:" at 113.69,-16.654 h1.52
  text ".VersionControl_RevNumber" at 126.543,-16.654 h1.52
  text "TID #:" at 57.099,-21.819 h1.52
  text ".TID" at 70.955,-21.819 h1.52
  text "LAYER NAME =" at -6.35,-22.098 h1.52
  text "PLOT NAME =" at -5.804,-27.034 h1.52
  text ".plot_File_Name" at 14.656,-27.034 h1.52
  text "GENERATED    :" at 57.15,-27.034 h1.52
  text ".Print_Date" at 79.235,-27.034 h1.52
  text ".Print_Time" at 97.752,-27.034 h1.52
  text "TEXAS INSTRUMENTS" at 129.87,-27.034 h1.52
M12 Stackup:
  drawing of 191 lines, arcs and shapes, not listed
  text "Layer" at 248.675,198.882 h1.52
  text "Name" at 259.086,198.882 h1.52
  text "Material" at 282.702,198.882 h1.52
  text "Thickness" at 304.54,198.882 h1.52
  text "Constant" at 321.046,198.882 h1.52
  text "Board Layer Stack" at 335.52,198.882 h1.52
  text "1" at 248.675,195.834 h1.52
  text "Top Overlay" at 259.086,195.834 h1.52
  text "2" at 248.675,192.786 h1.52
  text "Top Solder" at 259.086,192.786 h1.52
  text "Solder Resist" at 282.702,192.786 h1.52
  text "0.40mil" at 304.54,192.786 h1.52
  text "3.5" at 321.046,192.786 h1.52
  text "3" at 248.675,189.738 h1.52
  text "Top Layer" at 259.086,189.738 h1.52
  text "Copper" at 282.702,189.738 h1.52
  text "1.40mil" at 304.54,189.738 h1.52
  text "4" at 248.675,186.69 h1.52
  text "Dielectric1" at 259.086,186.69 h1.52
  text "FR-4" at 282.702,186.69 h1.52
  text "59.20mil" at 304.54,186.69 h1.52
  text "4.8" at 321.046,186.69 h1.52
  text "5" at 248.675,183.642 h1.52
  text "Bottom Layer" at 259.086,183.642 h1.52
  text "Copper" at 282.702,183.642 h1.52
  text "1.40mil" at 304.54,183.642 h1.52
  text "6" at 248.675,180.594 h1.52
  text "Bottom Solder" at 259.086,180.594 h1.52
  text "Solder Resist" at 282.702,180.594 h1.52
  text "0.40mil" at 304.54,180.594 h1.52
  text "3.5" at 321.046,180.594 h1.52
  text "7" at 248.675,177.546 h1.52
  text "Bottom Overlay" at 259.086,177.546 h1.52
Drill Drawing:
  circle w0.254: c144.369,19.733 r0.703
  lines w0.254: 143.666,47.482 145.071,47.482 145.071,48.887 143.666,48.887 143.666,47.482 ; 143.666,57.317 144.017,57.317 144.369,56.966 144.72,57.317 145.071,57.317 144.72,57.668 145.071,58.02 144.72,58.02 144.369,58.371 144.017,58.02 143.666,58.02 144.017,57.668 143.666,57.317 ; 143.666,82.256 144.369,82.607 145.071,82.256 144.72,82.958 145.071,83.661 144.369,83.31 143.666,83.661 144.017,82.958 143.666,82.256
  lines w0.305: 142.392,18.082 192.669,18.082 ; 142.392,84.469 192.669,84.469 ; 150.982,14.921 150.982,87.63 ; 159.418,14.921 159.418,87.63 ; 175.597,14.921 175.597,87.63 ; 182.185,14.921 182.185,87.63 ; 142.392,14.921 192.669,14.921 192.669,87.63 142.392,87.63 142.392,14.921
  text "Symbol" at 144.289,85.417 h1.83
  text "Quantity" at 151.93,85.417 h1.83
  text "Finished Hole Size" at 160.366,85.417 h1.83
  text "Plated" at 176.546,85.417 h1.83
  text "Hole Type" at 183.133,85.417 h1.83
  text "163" at 151.93,82.256 h1.52
  text "19.69mil (0.500mm)" at 160.366,82.256 h1.52
  text "PTH" at 176.546,82.256 h1.52
  text "Round" at 183.133,82.256 h1.52
  text "_" at 143.646,79.543 h1.41
  text "64" at 151.93,79.095 h1.52
  text "28.00mil (0.711mm)" at 160.366,79.095 h1.52
  text "PTH" at 176.546,79.095 h1.52
  text "Round" at 183.133,79.095 h1.52
  text "`" at 143.88,76.148 h1.41
  text "1" at 151.93,75.933 h1.52
  text "28.01mil (0.712mm)" at 160.366,75.933 h1.52
  text "PTH" at 176.546,75.933 h1.52
  text "Round" at 183.133,75.933 h1.52
  text "4" at 151.93,72.772 h1.52
  text "29.53mil (0.750mm)" at 160.366,72.772 h1.52
  text "PTH" at 176.546,72.772 h1.52
  text "Round" at 183.133,72.772 h1.52
  text "]" at 143.88,72.518 h1.41
  text "13" at 151.93,69.611 h1.52
  text "35.43mil (0.900mm)" at 160.366,69.611 h1.52
  text "PTH" at 176.546,69.611 h1.52
  text "Round" at 183.133,69.611 h1.52
  text "T" at 143.646,69.357 h1.41
  text "^" at 143.646,66.664 h1.41
  text "2" at 151.93,66.45 h1.52
  text "37.40mil (0.950mm)" at 160.366,66.45 h1.52
  text "PTH" at 176.546,66.45 h1.52
  text "Round" at 183.133,66.45 h1.52
  text "2" at 151.93,63.288 h1.52
  text "38.00mil (0.965mm)" at 160.366,63.288 h1.52
  text "PTH" at 176.546,63.288 h1.52
  text "Round" at 183.133,63.288 h1.52
  text "b" at 143.646,63.035 h1.41
  text "7" at 151.93,60.127 h1.52
  text "40.00mil (1.016mm)" at 160.366,60.127 h1.52
  text "PTH" at 176.546,60.127 h1.52
  text "Round" at 183.133,60.127 h1.52
  text "Q" at 143.646,59.873 h1.41
  text "2" at 151.93,56.966 h1.52
  text "40.16mil (1.020mm)" at 160.366,56.966 h1.52
  text "PTH" at 176.546,56.966 h1.52
  text "Round" at 183.133,56.966 h1.52
  text "4" at 151.93,53.805 h1.52
  text "41.34mil (1.050mm)" at 160.366,53.805 h1.52
  text "PTH" at 176.546,53.805 h1.52
  text "Round" at 183.133,53.805 h1.52
  text "S" at 143.646,53.551 h1.41
  text "14" at 151.93,50.643 h1.52
  text "43.31mil (1.100mm)" at 160.366,50.643 h1.52
  text "PTH" at 176.546,50.643 h1.52
  text "Round" at 183.133,50.643 h1.52
  text "[" at 143.88,50.39 h1.41
  text "4" at 151.93,47.482 h1.52
  text "49.21mil (1.250mm)" at 160.366,47.482 h1.52
  text "PTH" at 176.546,47.482 h1.52
  text "Round" at 183.133,47.482 h1.52
  text "15" at 151.93,44.321 h1.52
  text "50.00mil (1.270mm)" at 160.366,44.321 h1.52
  text "PTH" at 176.546,44.321 h1.52
  text "Round" at 183.133,44.321 h1.52
  text "Y" at 143.646,44.067 h1.41
  text "8" at 151.93,41.16 h1.52
  text "51.18mil (1.300mm)" at 160.366,41.16 h1.52
  text "PTH" at 176.546,41.16 h1.52
  text "Round" at 183.133,41.16 h1.52
  text "I" at 143.88,40.906 h1.41
  text "4" at 151.93,37.998 h1.52
  text "52.00mil (1.321mm)" at 160.366,37.998 h1.52
  text "PTH" at 176.546,37.998 h1.52
  text "Round" at 183.133,37.998 h1.52
  text "\" at 143.646,37.979 h1.41
  text "11" at 151.93,34.837 h1.52
  text "55.12mil (1.400mm)" at 160.366,34.837 h1.52
  text "PTH" at 176.546,34.837 h1.52
  text "Round" at 183.133,34.837 h1.52
  text "Z" at 143.646,34.583 h1.41
  text "6" at 151.93,31.676 h1.52
  text "59.06mil (1.500mm)" at 160.366,31.676 h1.52
  text "PTH" at 176.546,31.676 h1.52
  text "Round" at 183.133,31.676 h1.52
  text "W" at 143.646,31.422 h1.41
  text "18" at 151.93,28.515 h1.52
  text "62.99mil (1.600mm)" at 160.366,28.515 h1.52
  text "PTH" at 176.546,28.515 h1.52
  text "Round" at 183.133,28.515 h1.52
  text "J" at 143.646,28.261 h1.41
  text "4" at 151.93,25.353 h1.52
  text "78.74mil (2.000mm)" at 160.366,25.353 h1.52
  text "PTH" at 176.546,25.353 h1.52
  text "Round" at 183.133,25.353 h1.52
  text "P" at 143.646,25.1 h1.41
  text "3" at 151.93,22.192 h1.52
  text "80.00mil (2.032mm)" at 160.366,22.192 h1.52
  text "PTH" at 176.546,22.192 h1.52
  text "Round" at 183.133,22.192 h1.52
  text "i" at 143.88,21.938 h1.41
  text "8" at 151.93,19.031 h1.52
  text "126.00mil (3.200mm)" at 160.366,19.031 h1.52
  text "PTH" at 176.546,19.031 h1.52
  text "Round" at 183.133,19.031 h1.52
  text "357 Total" at 151.93,15.87 h1.52

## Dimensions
87.63,173.863 to 92.202,178.435 on M5 Assembly Top
87.63,173.863 to 92.202,178.435 on M5 Assembly Top
8.636,173.863 to 4.064,178.435 on M5 Assembly Top
8.636,173.863 to 4.064,178.435 on M5 Assembly Top
87.63,9.652 to 92.202,5.08 on M5 Assembly Top
87.63,9.652 to 92.202,5.08 on M5 Assembly Top
8.636,9.652 to 4.064,5.08 on M5 Assembly Top
8.636,9.652 to 4.064,5.08 on M5 Assembly Top
4.064,5.08 to 92.202,5.08 on M2 Board Dimensions
0,-10.16 to 25.4,-10.16 on M2 Board Dimensions
92.202,178.435 to 92.202,5.08 on M5 Assembly Top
